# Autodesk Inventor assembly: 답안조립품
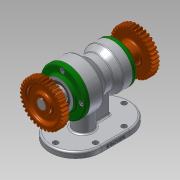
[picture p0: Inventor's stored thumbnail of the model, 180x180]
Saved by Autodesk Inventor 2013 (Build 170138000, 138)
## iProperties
Created: 2020-01
Part Number: 답안조립품
Document SubType Name: Assembly
Designer: Administrator
Author: Administrator
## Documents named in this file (13)
- C:\Users\Administrator\Desktop\700104V1018\답안조립품.iam
- C:\Users\Administrator\Desktop\700104V1018\본체.ipt
- C:\Users\Administrator\Desktop\700104V1018\뒤커버.ipt
- C:\Users\Administrator\Desktop\700104V1018\멈춤나사 M3.ipt
- C:\Users\Administrator\Desktop\700104V1018\베어링 6203.ipt
- C:\Users\Administrator\Desktop\700104V1018\베어링 6205.ipt
- C:\Users\Administrator\Desktop\700104V1018\볼트 M4.ipt
- C:\Users\Administrator\Desktop\700104V1018\스퍼기어.ipt
- C:\Users\Administrator\Desktop\700104V1018\앞커버.ipt
- C:\Users\Administrator\Desktop\700104V1018\오일 실 17 30 8.ipt
- C:\Users\Administrator\Desktop\700104V1018\오일 실 25 38 8.ipt
- C:\Users\Administrator\Desktop\700104V1018\축.ipt
- C:\Users\Administrator\Desktop\700104V1018\키 5 x 5 x 18.ipt
